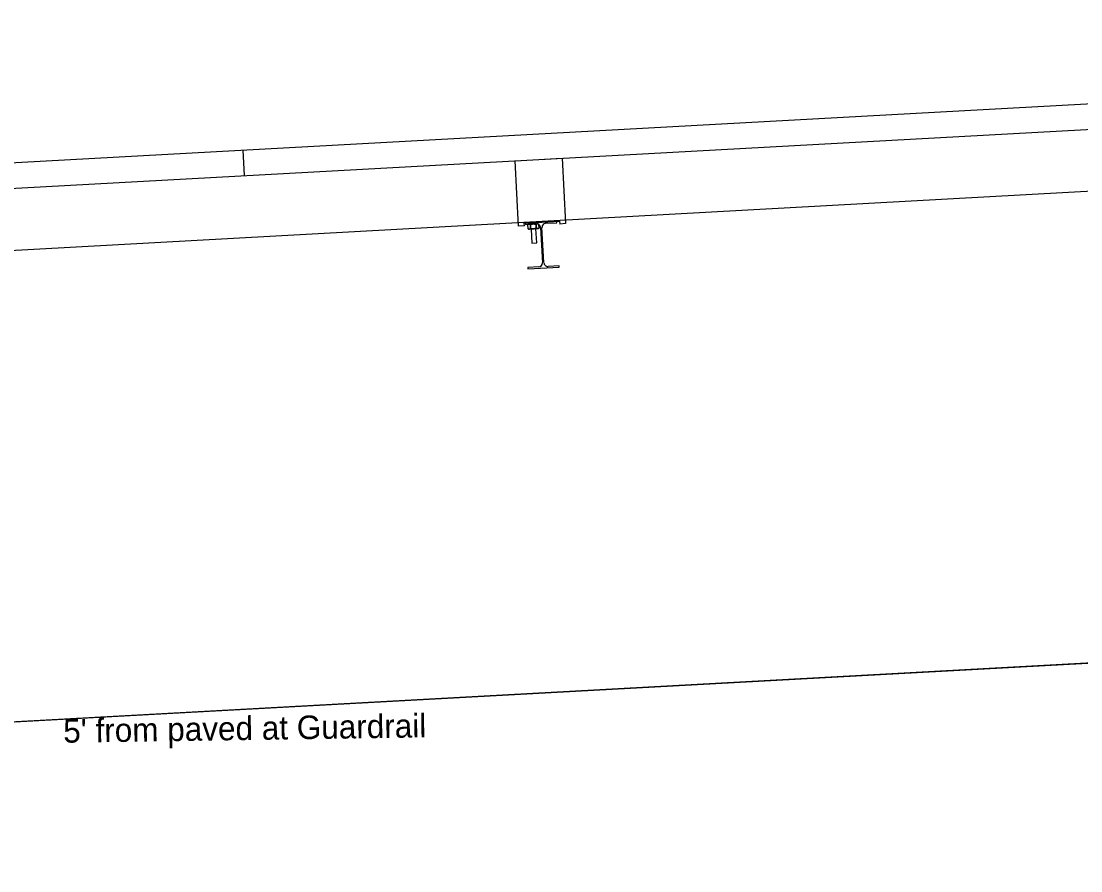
# Model space of a CAD drawing. Extents: x 17498307 to 17498862, y 7167523 to 7167641.
# Drawn here: x 17498380.48 to 17498391.73, y 7167548.4 to 7167557.41 of the extents above; entities that cross this region are included whole.
import ezdxf

# ---------------------------------------------------------------- set-up
doc = ezdxf.new("R2010")
doc.units = 0
for name, color, linetype in [('_CIVIL_CONSTRUCTION', 7, 'Continuous'), ('Draft_DNC', 7, 'Continuous'), ('dsnCellsHighwaySymbols', 7, 'Continuous'), ('TextAlignmentSml', 7, 'Continuous'), ('TL_ForeSlopeBarnRoof', 7, 'Continuous')]:
    doc.layers.add(name, color=color, linetype=linetype)

msp = doc.modelspace()

# ---------------------------------------------------------------- linework, layer by layer
at = {"layer": '_CIVIL_CONSTRUCTION'}
msp.add_line((17498404.485, 7167556.301), (17498357.079, 7167553.702), dxfattribs=at)
at = {"layer": 'Draft_DNC'}
msp.add_line((17498404.759, 7167551.308), (17498357.092, 7167548.701), dxfattribs=at)
at = {"layer": 'dsnCellsHighwaySymbols'}
for p, q in [((17498385.724, 7167555.933), (17498386.223, 7167555.96)), ((17498386.223, 7167555.96), (17498386.261, 7167555.265)), ((17498385.762, 7167555.237), (17498385.724, 7167555.933)), ((17498385.822, 7167555.272), (17498386.197, 7167555.293)), ((17498386.166, 7167555.291), (17498385.833, 7167555.273)), ((17498386.166, 7167555.291), (17498385.833, 7167555.273)), ((17498386.166, 7167555.275), (17498386.166, 7167555.291)), ((17498386.166, 7167555.275), (17498386.166, 7167555.291)), ((17498386.197, 7167555.293), (17498386.199, 7167555.261)), ((17498385.824, 7167555.241), (17498385.762, 7167555.237)), ((17498385.824, 7167555.241), (17498385.822, 7167555.272)), ((17498385.833, 7167555.273), (17498385.834, 7167555.257)), ((17498385.833, 7167555.273), (17498385.834, 7167555.257)), ((17498385.834, 7167555.257), (17498385.951, 7167555.263)), ((17498385.834, 7167555.257), (17498385.951, 7167555.263)), ((17498385.865, 7167555.259), (17498385.857, 7167555.253)), ((17498385.865, 7167555.259), (17498385.857, 7167555.253)), ((17498385.857, 7167555.253), (17498385.859, 7167555.212)), ((17498385.857, 7167555.253), (17498385.859, 7167555.212)), ((17498385.859, 7167555.212), (17498385.868, 7167555.207)), ((17498385.875, 7167555.207), (17498385.868, 7167555.207)), ((17498385.971, 7167555.212), (17498385.875, 7167555.207)), ((17498385.887, 7167555.255), (17498385.889, 7167555.213)), ((17498385.889, 7167555.213), (17498385.887, 7167555.255)), ((17498385.887, 7167555.255), (17498385.889, 7167555.213)), ((17498385.894, 7167555.208), (17498385.902, 7167555.057)), ((17498385.954, 7167555.06), (17498385.946, 7167555.211)), ((17498385.947, 7167555.258), (17498385.949, 7167555.216)), ((17498385.949, 7167555.216), (17498385.947, 7167555.258)), ((17498385.947, 7167555.258), (17498385.949, 7167555.216)), ((17498385.971, 7167555.212), (17498385.979, 7167555.218)), ((17498385.979, 7167555.218), (17498385.977, 7167555.256)), ((17498385.977, 7167555.256), (17498385.979, 7167555.218)), ((17498385.995, 7167555.224), (17498386.015, 7167554.85)), ((17498385.995, 7167555.224), (17498386.015, 7167554.85)), ((17498386.031, 7167554.851), (17498386.01, 7167555.225)), ((17498386.031, 7167554.851), (17498386.01, 7167555.225)), ((17498386.049, 7167555.269), (17498386.166, 7167555.275)), ((17498386.049, 7167555.269), (17498386.166, 7167555.275)), ((17498386.261, 7167555.265), (17498386.199, 7167555.261)), ((17498385.902, 7167555.057), (17498385.954, 7167555.06)), ((17498385.976, 7167554.806), (17498385.859, 7167554.799)), ((17498385.976, 7167554.806), (17498385.859, 7167554.799)), ((17498385.859, 7167554.799), (17498385.86, 7167554.784)), ((17498385.859, 7167554.799), (17498385.86, 7167554.784)), ((17498385.86, 7167554.784), (17498386.192, 7167554.802)), ((17498385.86, 7167554.784), (17498386.192, 7167554.802)), ((17498386.192, 7167554.818), (17498386.075, 7167554.811)), ((17498386.192, 7167554.818), (17498386.075, 7167554.811)), ((17498386.192, 7167554.802), (17498386.192, 7167554.818)), ((17498386.192, 7167554.802), (17498386.192, 7167554.818))]:
    msp.add_line(p, q, dxfattribs=at)
for points in [[(17498385.859, 7167555.212), (17498385.868, 7167555.207), (17498385.875, 7167555.207), (17498385.971, 7167555.212), (17498385.979, 7167555.218)], [(17498385.951, 7167555.263), (17498385.865, 7167555.259), (17498385.865, 7167555.259)], [(17498385.977, 7167555.256), (17498385.977, 7167555.256)]]:
    msp.add_lwpolyline(points, dxfattribs=at)
msp.add_lwpolyline([(17498385.894, 7167555.208), (17498385.902, 7167555.057), (17498385.954, 7167555.06), (17498385.946, 7167555.211)], close=True, dxfattribs=at)
for centre, start, end in [((17498385.953, 7167555.222), 54.0245, 93.1404), ((17498385.953, 7167555.222), 3.1312, 93.1404), ((17498385.953, 7167555.222), 3.1312, 93.1404), ((17498386.052, 7167555.227), 93.1452, 183.1342), ((17498386.052, 7167555.227), 93.1452, 183.1342), ((17498385.973, 7167554.847), 273.1452, 3.1342), ((17498385.973, 7167554.847), 273.1452, 3.1342), ((17498386.072, 7167554.853), 183.1312, 273.1404), ((17498386.072, 7167554.853), 183.1312, 273.1404)]:
    msp.add_arc(centre, 0.0417, start, end, dxfattribs=at)
for points in [[(17498385.857, 7167555.253), (17498385.859, 7167555.254), (17498385.862, 7167555.256), (17498385.868, 7167555.259), (17498385.876, 7167555.259), (17498385.882, 7167555.257), (17498385.886, 7167555.255), (17498385.887, 7167555.255)], [(17498385.887, 7167555.255), (17498385.886, 7167555.255), (17498385.882, 7167555.257), (17498385.876, 7167555.259), (17498385.868, 7167555.259), (17498385.862, 7167555.256), (17498385.859, 7167555.254), (17498385.857, 7167555.253)], [(17498385.887, 7167555.255), (17498385.886, 7167555.255), (17498385.882, 7167555.257), (17498385.876, 7167555.259), (17498385.868, 7167555.259), (17498385.862, 7167555.256), (17498385.859, 7167555.254), (17498385.857, 7167555.253)], [(17498385.859, 7167555.212), (17498385.861, 7167555.211), (17498385.865, 7167555.209), (17498385.871, 7167555.207), (17498385.878, 7167555.207), (17498385.885, 7167555.21), (17498385.888, 7167555.212), (17498385.889, 7167555.213)], [(17498385.889, 7167555.213), (17498385.888, 7167555.212), (17498385.885, 7167555.21), (17498385.878, 7167555.207), (17498385.871, 7167555.207), (17498385.865, 7167555.209), (17498385.861, 7167555.211), (17498385.859, 7167555.212)], [(17498385.859, 7167555.212), (17498385.861, 7167555.211), (17498385.865, 7167555.209), (17498385.871, 7167555.207), (17498385.878, 7167555.207), (17498385.885, 7167555.21), (17498385.888, 7167555.212), (17498385.889, 7167555.213)], [(17498385.887, 7167555.255), (17498385.892, 7167555.256), (17498385.9, 7167555.259), (17498385.915, 7167555.262), (17498385.931, 7167555.262), (17498385.942, 7167555.259), (17498385.947, 7167555.258)], [(17498385.947, 7167555.258), (17498385.942, 7167555.259), (17498385.931, 7167555.262), (17498385.915, 7167555.262), (17498385.9, 7167555.259), (17498385.892, 7167555.256), (17498385.887, 7167555.255)], [(17498385.947, 7167555.258), (17498385.942, 7167555.259), (17498385.931, 7167555.262), (17498385.915, 7167555.262), (17498385.9, 7167555.259), (17498385.892, 7167555.256), (17498385.887, 7167555.255)], [(17498385.889, 7167555.213), (17498385.895, 7167555.212), (17498385.906, 7167555.21), (17498385.921, 7167555.209), (17498385.936, 7167555.212), (17498385.945, 7167555.215), (17498385.949, 7167555.216)], [(17498385.949, 7167555.216), (17498385.945, 7167555.215), (17498385.936, 7167555.212), (17498385.921, 7167555.209), (17498385.906, 7167555.21), (17498385.895, 7167555.212), (17498385.889, 7167555.213)], [(17498385.889, 7167555.213), (17498385.895, 7167555.212), (17498385.906, 7167555.21), (17498385.921, 7167555.209), (17498385.936, 7167555.212), (17498385.945, 7167555.215), (17498385.949, 7167555.216)], [(17498385.957, 7167555.263), (17498385.956, 7167555.262), (17498385.952, 7167555.262), (17498385.949, 7167555.26), (17498385.947, 7167555.258)], [(17498385.949, 7167555.216), (17498385.952, 7167555.215), (17498385.957, 7167555.213), (17498385.966, 7167555.212), (17498385.973, 7167555.214), (17498385.977, 7167555.217), (17498385.979, 7167555.218)], [(17498385.979, 7167555.218), (17498385.977, 7167555.217), (17498385.973, 7167555.214), (17498385.966, 7167555.212), (17498385.957, 7167555.213), (17498385.952, 7167555.215), (17498385.949, 7167555.216)], [(17498385.949, 7167555.216), (17498385.952, 7167555.215), (17498385.957, 7167555.213), (17498385.966, 7167555.212), (17498385.973, 7167555.214), (17498385.977, 7167555.217), (17498385.979, 7167555.218)]]:
    msp.add_open_spline(points, degree=3, dxfattribs=at)
at = {"layer": 'TextAlignmentSml'}
for p, q in [((17498366.665, 7167555.159), (17498407.803, 7167557.414)), ((17498366.68, 7167554.889), (17498407.818, 7167557.144)), ((17498382.853, 7167555.775), (17498382.838, 7167556.046)), ((17498385.724, 7167555.933), (17498386.223, 7167555.96)), ((17498386.223, 7167555.96), (17498386.261, 7167555.265)), ((17498385.762, 7167555.237), (17498385.724, 7167555.933)), ((17498385.822, 7167555.272), (17498386.197, 7167555.293)), ((17498386.166, 7167555.291), (17498385.833, 7167555.273)), ((17498386.166, 7167555.275), (17498386.166, 7167555.291)), ((17498386.197, 7167555.293), (17498386.199, 7167555.261)), ((17498385.824, 7167555.241), (17498385.762, 7167555.237)), ((17498385.824, 7167555.241), (17498385.822, 7167555.272)), ((17498385.833, 7167555.273), (17498385.834, 7167555.257)), ((17498385.834, 7167555.257), (17498385.951, 7167555.263)), ((17498385.865, 7167555.259), (17498385.857, 7167555.253)), ((17498385.857, 7167555.253), (17498385.859, 7167555.212)), ((17498385.859, 7167555.212), (17498385.868, 7167555.207)), ((17498385.875, 7167555.207), (17498385.868, 7167555.207)), ((17498385.971, 7167555.212), (17498385.875, 7167555.207)), ((17498385.887, 7167555.255), (17498385.889, 7167555.213)), ((17498385.894, 7167555.208), (17498385.902, 7167555.057)), ((17498385.954, 7167555.06), (17498385.946, 7167555.211)), ((17498385.947, 7167555.258), (17498385.949, 7167555.216)), ((17498385.971, 7167555.212), (17498385.979, 7167555.218)), ((17498385.977, 7167555.256), (17498385.979, 7167555.218)), ((17498385.995, 7167555.224), (17498386.015, 7167554.85)), ((17498386.031, 7167554.851), (17498386.01, 7167555.225)), ((17498386.049, 7167555.269), (17498386.166, 7167555.275)), ((17498386.261, 7167555.265), (17498386.199, 7167555.261)), ((17498385.902, 7167555.057), (17498385.954, 7167555.06)), ((17498385.976, 7167554.806), (17498385.859, 7167554.799)), ((17498385.859, 7167554.799), (17498385.86, 7167554.784)), ((17498385.86, 7167554.784), (17498386.192, 7167554.802)), ((17498386.192, 7167554.818), (17498386.075, 7167554.811)), ((17498386.192, 7167554.802), (17498386.192, 7167554.818))]:
    msp.add_line(p, q, dxfattribs=at)
for centre, start, end in [((17498385.953, 7167555.222), 3.1312, 93.1404), ((17498386.052, 7167555.227), 93.1452, 183.1342), ((17498385.973, 7167554.847), 273.1452, 3.1342), ((17498386.072, 7167554.853), 183.1312, 273.1404)]:
    msp.add_arc(centre, 0.0417, start, end, dxfattribs=at)
for points in [[(17498385.887, 7167555.255), (17498385.886, 7167555.255), (17498385.882, 7167555.257), (17498385.876, 7167555.259), (17498385.868, 7167555.259), (17498385.862, 7167555.256), (17498385.859, 7167555.254), (17498385.857, 7167555.253)], [(17498385.859, 7167555.212), (17498385.861, 7167555.211), (17498385.865, 7167555.209), (17498385.871, 7167555.207), (17498385.878, 7167555.207), (17498385.885, 7167555.21), (17498385.888, 7167555.212), (17498385.889, 7167555.213)], [(17498385.947, 7167555.258), (17498385.942, 7167555.259), (17498385.931, 7167555.262), (17498385.915, 7167555.262), (17498385.9, 7167555.259), (17498385.892, 7167555.256), (17498385.887, 7167555.255)], [(17498385.889, 7167555.213), (17498385.895, 7167555.212), (17498385.906, 7167555.21), (17498385.921, 7167555.209), (17498385.936, 7167555.212), (17498385.945, 7167555.215), (17498385.949, 7167555.216)], [(17498385.957, 7167555.263), (17498385.956, 7167555.262), (17498385.952, 7167555.262), (17498385.949, 7167555.26), (17498385.947, 7167555.258)], [(17498385.949, 7167555.216), (17498385.952, 7167555.215), (17498385.957, 7167555.213), (17498385.966, 7167555.212), (17498385.973, 7167555.214), (17498385.977, 7167555.217), (17498385.979, 7167555.218)]]:
    msp.add_open_spline(points, degree=3, dxfattribs=at)
at = {"layer": 'TL_ForeSlopeBarnRoof'}
msp.add_lwpolyline([(17498337.156, 7167548.396), (17498357.092, 7167548.701), (17498380.925, 7167550.005), (17498404.759, 7167551.308), (17498476.199, 7167552.37)], dxfattribs=at)

# ---------------------------------------------------------------- texts
at = {"layer": 'Draft_DNC'}
msp.add_text("5' from paved at Guardrail", height=0.25, rotation=0.8552, dxfattribs=at).set_placement((17498380.929, 7167549.755))

doc.saveas('drawing.dxf')
